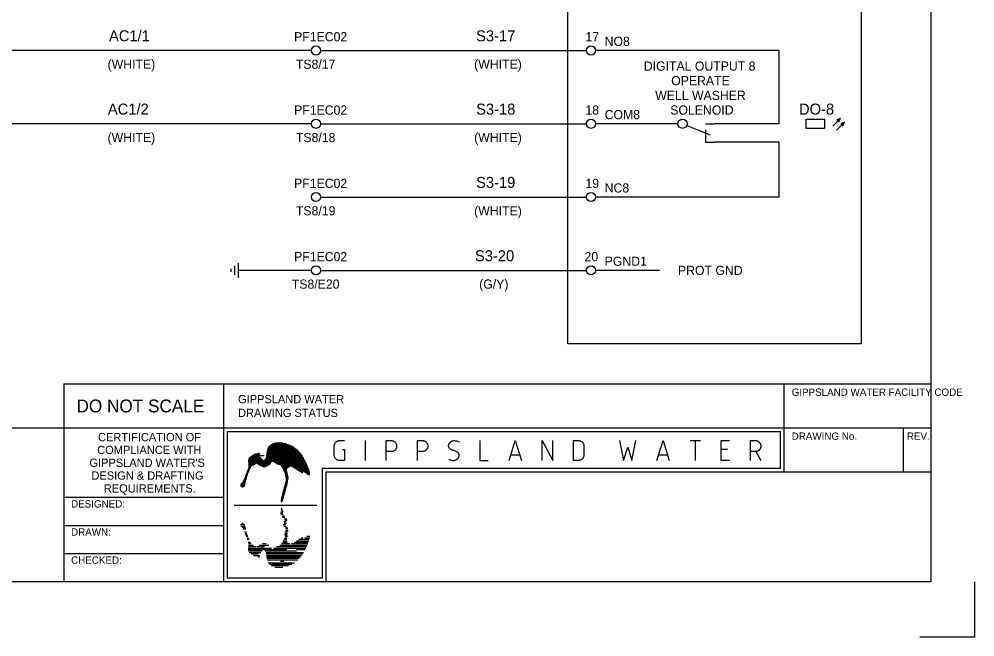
# Model space of a CAD drawing. Extents: x 0 to 841, y 0 to 594.
# Drawn here: x 580.3 to 841, y 0 to 168.6 of the extents above; entities that cross this region are included whole.
import ezdxf

# ---------------------------------------------------------------- set-up
doc = ezdxf.new("R2010")
doc.units = 0
for name, color, linetype in [('A1BORDER', 7, 'Continuous'), ('Level 1', 7, 'Continuous'), ('Level 10', 7, 'Continuous')]:
    doc.layers.add(name, color=color, linetype=linetype)

msp = doc.modelspace()

# ---------------------------------------------------------------- linework, layer by layer
at = {"layer": 'A1BORDER'}
for p, q in [((829, 581), (829, 15)), ((592.5, 69), (592.5, 15)), ((592.5, 69), (829, 69)), ((636, 69), (636, 15)), ((789, 45), (789, 69)), ((28, 57), (829, 57)), ((637, 56), (788, 56)), ((637, 56), (637, 16)), ((788, 46), (788, 56)), ((821.5, 45), (821.5, 57)), ((648.74, 52.32), (654.24, 52.32)), ((649.02, 52.52), (653.76, 52.52)), ((649.39, 52.72), (653.15, 52.72)), ((650.01, 52.92), (652.2, 52.92)), ((644.18, 49.72), (645.89, 49.72)), ((644.54, 49.92), (645.36, 49.92)), ((645.37, 50.12), (645.86, 50.12)), ((647.71, 49.72), (657.31, 49.72)), ((647.75, 49.92), (657.17, 49.92)), ((647.78, 50.12), (657.02, 50.12)), ((647.81, 50.32), (656.86, 50.32)), ((647.85, 50.52), (656.69, 50.52)), ((647.88, 50.72), (656.5, 50.72)), ((647.91, 50.92), (656.3, 50.92)), ((647.96, 51.12), (656.08, 51.12)), ((648.03, 51.32), (655.85, 51.32)), ((648.12, 51.52), (655.59, 51.52)), ((648.23, 51.72), (655.31, 51.72)), ((648.37, 51.92), (655, 51.92)), ((648.53, 52.12), (654.64, 52.12)), ((642.73, 48.12), (658.25, 48.12)), ((642.74, 47.92), (658.35, 47.92)), ((642.75, 48.32), (646.79, 48.32)), ((642.79, 47.72), (649.08, 47.72)), ((642.81, 48.52), (646.55, 48.52)), ((642.83, 47.52), (648.95, 47.52)), ((642.85, 47.31), (644.88, 47.31)), ((642.87, 47.12), (644.57, 47.12)), ((642.9, 48.72), (646.37, 48.72)), ((643.04, 48.92), (646.16, 48.92)), ((643.26, 49.12), (645.9, 49.12)), ((643.54, 49.32), (645.57, 49.32)), ((643.85, 49.52), (647.09, 49.52)), ((645.14, 47.31), (648.83, 47.31)), ((645.49, 47.12), (648.67, 47.12)), ((647.19, 48.32), (658.14, 48.32)), ((647.42, 48.52), (658.03, 48.52)), ((647.54, 48.72), (657.92, 48.72)), ((647.61, 48.92), (657.8, 48.92)), ((647.63, 49.12), (657.68, 49.12)), ((647.66, 49.32), (657.57, 49.32)), ((647.69, 49.52), (657.44, 49.52)), ((649.72, 47.72), (658.45, 47.72)), ((650.12, 47.52), (658.55, 47.52)), ((650.48, 47.31), (658.64, 47.31)), ((650.87, 47.12), (658.73, 47.12)), ((642.21, 44.52), (642.69, 44.52)), ((642.28, 44.72), (642.76, 44.72)), ((642.35, 44.92), (642.83, 44.92)), ((642.43, 45.12), (642.9, 45.12)), ((642.5, 45.32), (643, 45.32)), ((642.57, 45.52), (643.1, 45.52)), ((642.65, 45.72), (643.2, 45.72)), ((642.72, 45.92), (643.3, 45.92)), ((642.79, 46.12), (643.4, 46.12)), ((642.84, 46.32), (643.5, 46.32)), ((642.87, 46.52), (643.6, 46.52)), ((642.88, 46.92), (644.23, 46.92)), ((642.88, 46.72), (643.83, 46.72)), ((645.76, 46.92), (648.42, 46.92)), ((646.05, 46.72), (648.11, 46.72)), ((646.62, 46.52), (647.67, 46.52)), ((651.36, 46.92), (658.82, 46.92)), ((651.76, 46.72), (658.9, 46.72)), ((651.88, 46.52), (654.15, 46.52)), ((651.99, 46.32), (653.71, 46.32)), ((652.1, 46.12), (653.52, 46.12)), ((652.2, 45.92), (653.4, 45.92)), ((652.31, 45.72), (653.33, 45.72)), ((652.41, 45.52), (653.31, 45.52)), ((652.5, 45.32), (653.34, 45.32)), ((652.6, 45.12), (653.38, 45.12)), ((652.69, 44.92), (653.41, 44.92)), ((652.78, 44.72), (653.44, 44.72)), ((652.83, 44.52), (653.48, 44.52)), ((654.57, 46.52), (658.99, 46.52)), ((655, 46.32), (659.07, 46.32)), ((655.31, 46.12), (659.14, 46.12)), ((655.62, 45.92), (659.22, 45.92)), ((655.93, 45.72), (659.29, 45.72)), ((656.24, 45.52), (659.35, 45.52)), ((656.55, 45.32), (659.42, 45.32)), ((656.86, 45.12), (657.74, 45.12)), ((657.17, 44.92), (657.68, 44.92)), ((657.51, 44.72), (657.54, 44.72)), ((657.91, 45.12), (659.48, 45.12)), ((658.19, 44.92), (659.54, 44.92)), ((658.47, 44.72), (659.59, 44.72)), ((658.75, 44.52), (659.58, 44.52)), ((663, 46), (788, 46)), ((663, 16), (663, 46)), ((664, 45), (829, 45)), ((664, 15), (664, 45)), ((640.73, 41.72), (641.95, 41.72)), ((640.9, 41.92), (641.97, 41.92)), ((641.1, 42.12), (642, 42.12)), ((641.25, 42.31), (642.04, 42.31)), ((641.37, 42.52), (642.09, 42.52)), ((641.46, 42.72), (642.15, 42.72)), ((641.55, 42.92), (642.2, 42.92)), ((641.64, 43.12), (642.25, 43.12)), ((641.73, 43.32), (642.3, 43.32)), ((641.82, 43.51), (642.35, 43.51)), ((641.91, 43.72), (642.41, 43.72)), ((641.99, 43.92), (642.48, 43.92)), ((642.06, 44.12), (642.55, 44.12)), ((642.13, 44.32), (642.62, 44.32)), ((652.79, 41.72), (653.41, 41.72)), ((652.85, 41.92), (653.45, 41.92)), ((652.86, 44.32), (653.53, 44.32)), ((652.89, 44.12), (653.57, 44.12)), ((652.9, 42.12), (653.49, 42.12)), ((652.91, 43.92), (653.62, 43.92)), ((652.94, 43.72), (653.67, 43.72)), ((652.95, 42.31), (653.53, 42.31)), ((652.97, 43.51), (653.71, 43.51)), ((652.99, 42.52), (653.57, 42.52)), ((653, 43.32), (653.69, 43.32)), ((653.02, 43.12), (653.67, 43.12)), ((653.03, 42.72), (653.61, 42.72)), ((653.05, 42.92), (653.64, 42.92)), ((659.02, 44.32), (659.47, 44.32)), ((640.62, 41.32), (641.88, 41.32)), ((640.63, 41.52), (641.93, 41.52)), ((640.72, 41.12), (641.73, 41.12)), ((641.03, 40.92), (641.43, 40.92)), ((652.09, 39.12), (652.72, 39.12)), ((652.14, 39.32), (652.77, 39.32)), ((652.2, 39.52), (652.82, 39.52)), ((652.25, 39.72), (652.88, 39.72)), ((652.3, 39.92), (652.93, 39.92)), ((652.36, 40.12), (652.99, 40.12)), ((652.41, 40.32), (653.04, 40.32)), ((652.47, 40.52), (653.1, 40.52)), ((652.52, 40.72), (653.15, 40.72)), ((652.57, 40.92), (653.2, 40.92)), ((652.63, 41.12), (653.26, 41.12)), ((652.68, 41.32), (653.31, 41.32)), ((652.74, 41.52), (653.37, 41.52)), ((636, 38), (592.5, 38)), ((651.63, 37.32), (652.23, 37.32)), ((651.64, 37.12), (652.17, 37.12)), ((651.65, 37.52), (652.28, 37.52)), ((651.71, 37.72), (652.34, 37.72)), ((651.76, 37.92), (652.39, 37.92)), ((651.79, 36.92), (651.9, 36.92)), ((651.82, 38.12), (652.44, 38.12)), ((651.87, 38.32), (652.5, 38.32)), ((651.92, 38.52), (652.55, 38.52)), ((651.98, 38.72), (652.61, 38.72)), ((652.03, 38.92), (652.66, 38.92)), ((638.93, 35.98), (661.47, 35.98)), ((651.63, 34.64), (652.23, 34.64)), ((651.71, 34.24), (652.34, 34.24)), ((651.79, 35.04), (651.9, 35.04)), ((651.54, 33.84), (652.17, 33.84)), ((651.65, 33.44), (652.28, 33.44)), ((652.03, 33.04), (652.66, 33.04)), ((652.14, 32.64), (652.77, 32.64)), ((652.47, 31.44), (653.1, 31.44)), ((652.66, 32.24), (653.29, 32.24)), ((652.77, 31.84), (653.4, 31.84)), ((636, 30.34), (592.5, 30.34)), ((640.62, 30.64), (641.88, 30.64)), ((640.73, 30.24), (641.95, 30.24)), ((641.03, 31.04), (641.43, 31.04)), ((641.1, 29.84), (642, 29.84)), ((641.37, 29.44), (642.09, 29.44)), ((652.34, 30.64), (652.97, 30.64)), ((652.45, 30.24), (653.07, 30.24)), ((652.57, 31.04), (653.2, 31.04)), ((652.9, 29.84), (653.49, 29.84)), ((652.99, 29.44), (653.57, 29.44)), ((653.05, 29.04), (653.64, 29.04)), ((641.73, 28.64), (642.3, 28.64)), ((641.91, 28.24), (642.41, 28.24)), ((642.06, 27.84), (642.55, 27.84)), ((642.21, 27.44), (642.69, 27.44)), ((642.35, 27.04), (642.83, 27.04)), ((642.5, 26.64), (643, 26.64)), ((652.31, 26.24), (653.33, 26.24)), ((652.5, 26.64), (653.34, 26.64)), ((652.66, 27.84), (653.35, 27.84)), ((652.69, 27.04), (653.41, 27.04)), ((652.72, 28.24), (653.44, 28.24)), ((652.77, 28.64), (653.46, 28.64)), ((652.83, 27.44), (653.48, 27.44)), ((655.93, 26.24), (659.29, 26.24)), ((656.55, 26.64), (659.42, 26.64)), ((657.17, 27.04), (657.68, 27.04)), ((658.19, 27.04), (659.54, 27.04)), ((658.75, 27.44), (659.58, 27.44)), ((642.73, 23.84), (653.27, 23.84)), ((642.79, 25.84), (643.4, 25.84)), ((642.79, 24.24), (649.08, 24.24)), ((642.85, 24.65), (644.88, 24.65)), ((642.87, 25.44), (643.6, 25.44)), ((642.88, 25.04), (644.23, 25.04)), ((645.14, 24.65), (647.18, 24.65)), ((645.76, 25.04), (648.42, 25.04)), ((646.62, 25.44), (647.67, 25.44)), ((649.72, 24.24), (658.45, 24.24)), ((650.48, 24.65), (658.64, 24.65)), ((651.36, 25.04), (658.82, 25.04)), ((651.88, 25.44), (654.15, 25.44)), ((652.1, 25.84), (653.52, 25.84)), ((654.57, 25.44), (658.99, 25.44)), ((655.31, 25.84), (659.14, 25.84)), ((655.94, 23.84), (658.25, 23.84)), ((636, 22.67), (592.5, 22.67)), ((642.81, 23.44), (646.55, 23.44)), ((643.04, 23.04), (646.16, 23.04)), ((643.54, 22.64), (645.57, 22.64)), ((644.18, 22.24), (645.89, 22.24)), ((645.37, 21.84), (645.86, 21.84)), ((647.42, 23.44), (655.89, 23.44)), ((647.61, 23.04), (657.8, 23.04)), ((647.66, 22.64), (657.57, 22.64)), ((647.71, 22.24), (657.31, 22.24)), ((647.78, 21.84), (657.02, 21.84)), ((647.85, 21.44), (656.69, 21.44)), ((647.91, 21.04), (656.3, 21.04)), ((648.23, 20.24), (655.31, 20.24)), ((648.53, 19.84), (654.64, 19.84)), ((649.02, 19.44), (653.76, 19.44)), ((650.01, 19.04), (652.2, 19.04)), ((651.57, 20.64), (652.44, 20.64)), ((663, 16), (637, 16)), ((829, 15), (28, 15)), ((829, 15), (829, 15)), ((841, 0), (841, 15)), ((826, 0), (841, 0))]:
    msp.add_line(p, q, dxfattribs=at)
for points in [[(668.49, 51.15), (669.06, 51.15), (669.06, 48.16), (667.64, 48.16), (667.51, 48.16), (667.39, 48.18), (667.28, 48.21), (667.15, 48.25), (667.04, 48.3), (666.93, 48.36), (666.82, 48.43), (666.73, 48.51), (666.64, 48.6), (666.55, 48.7), (666.48, 48.8), (666.41, 48.91), (666.35, 49.02), (666.31, 49.14), (666.27, 49.27), (666.24, 49.39), (666.22, 49.52), (666.22, 49.66), (666.22, 52.05), (666.22, 52.18), (666.24, 52.31), (666.27, 52.43), (666.31, 52.56), (666.35, 52.67), (666.41, 52.79), (666.48, 52.9), (666.55, 53), (666.64, 53.1), (666.73, 53.19), (666.82, 53.27), (666.93, 53.34), (667.04, 53.4), (667.15, 53.45), (667.28, 53.49), (667.39, 53.52), (667.51, 53.54), (667.64, 53.54), (669.06, 53.54)], [(674.74, 48.16), (674.74, 53.54)], [(680.42, 48.16), (680.42, 53.54), (681.84, 53.54), (681.96, 53.54), (682.08, 53.52), (682.2, 53.49), (682.32, 53.45), (682.43, 53.4), (682.54, 53.34), (682.65, 53.27), (682.74, 53.19), (682.84, 53.1), (682.92, 53), (682.99, 52.9), (683.06, 52.79), (683.12, 52.67), (683.17, 52.56), (683.21, 52.43), (683.23, 52.31), (683.25, 52.18), (683.26, 52.05), (683.25, 51.91), (683.23, 51.78), (683.21, 51.66), (683.17, 51.53), (683.12, 51.42), (683.06, 51.3), (682.99, 51.19), (682.92, 51.09), (682.84, 50.99), (682.74, 50.9), (682.65, 50.82), (682.54, 50.75), (682.43, 50.69), (682.32, 50.64), (682.2, 50.6), (682.08, 50.57), (681.96, 50.55), (681.84, 50.55), (680.42, 50.55)], [(688.93, 48.16), (688.93, 53.54), (690.35, 53.54), (690.47, 53.54), (690.59, 53.52), (690.71, 53.49), (690.83, 53.45), (690.94, 53.4), (691.05, 53.34), (691.16, 53.27), (691.26, 53.19), (691.35, 53.1), (691.43, 53), (691.51, 52.9), (691.57, 52.79), (691.63, 52.67), (691.68, 52.56), (691.72, 52.43), (691.75, 52.31), (691.76, 52.18), (691.77, 52.05), (691.76, 51.91), (691.75, 51.78), (691.72, 51.66), (691.68, 51.53), (691.63, 51.42), (691.57, 51.3), (691.51, 51.19), (691.43, 51.09), (691.35, 50.99), (691.26, 50.9), (691.16, 50.82), (691.05, 50.75), (690.94, 50.69), (690.83, 50.64), (690.71, 50.6), (690.59, 50.57), (690.47, 50.55), (690.35, 50.55), (688.93, 50.55)], [(697.45, 48.46), (697.67, 48.36), (697.9, 48.27), (698.12, 48.21), (698.36, 48.17), (698.6, 48.16), (698.84, 48.16), (698.87, 48.16), (699.03, 48.18), (699.18, 48.21), (699.33, 48.26), (699.48, 48.32), (699.62, 48.4), (699.72, 48.46), (699.81, 48.53), (699.9, 48.61), (699.98, 48.69), (700.05, 48.78), (700.11, 48.88), (700.17, 48.99), (700.22, 49.09), (700.25, 49.21), (700.28, 49.32), (700.29, 49.36), (700.3, 49.44), (700.3, 49.52), (700.3, 49.61), (700.29, 49.69), (700.27, 49.77), (700.25, 49.86), (700.22, 49.93), (700.18, 50.01), (700.14, 50.09), (700.09, 50.15), (700.04, 50.21), (700.01, 50.25), (699.85, 50.39), (699.69, 50.51), (699.52, 50.61), (699.34, 50.7), (699.15, 50.78), (698.95, 50.83), (698.87, 50.85), (698.68, 50.9), (698.49, 50.96), (698.3, 51.04), (698.12, 51.14), (697.96, 51.26), (697.8, 51.39), (697.73, 51.45), (697.67, 51.51), (697.62, 51.57), (697.58, 51.64), (697.53, 51.71), (697.5, 51.79), (697.47, 51.87), (697.46, 51.95), (697.44, 52.04), (697.43, 52.12), (697.43, 52.21), (697.44, 52.29), (697.45, 52.35), (697.47, 52.46), (697.51, 52.58), (697.55, 52.69), (697.61, 52.79), (697.67, 52.89), (697.74, 52.99), (697.82, 53.07), (697.9, 53.15), (697.99, 53.23), (698.02, 53.24), (698.15, 53.33), (698.3, 53.4), (698.44, 53.45), (698.6, 53.5), (698.75, 53.52), (698.87, 53.54), (699.11, 53.55), (699.35, 53.53), (699.58, 53.49), (699.82, 53.43), (700.04, 53.35), (700.27, 53.25)], [(705.96, 53.54), (705.96, 48.16), (708.23, 48.16)], [(713.91, 48.16), (715.61, 53.54), (717.32, 48.16)], [(722.99, 48.16), (722.99, 53.54), (725.83, 48.16), (725.83, 53.54)], [(731.52, 48.16), (731.52, 53.54), (732.94, 53.54), (733.06, 53.54), (733.18, 53.52), (733.3, 53.49), (733.42, 53.45), (733.53, 53.4), (733.64, 53.34), (733.75, 53.27), (733.84, 53.19), (733.94, 53.1), (734.02, 53), (734.09, 52.9), (734.16, 52.79), (734.22, 52.67), (734.27, 52.56), (734.31, 52.43), (734.33, 52.31), (734.35, 52.18), (734.36, 52.05), (734.36, 49.66), (734.35, 49.52), (734.33, 49.39), (734.31, 49.27), (734.27, 49.14), (734.22, 49.02), (734.16, 48.91), (734.09, 48.8), (734.02, 48.7), (733.94, 48.6), (733.84, 48.51), (733.75, 48.43), (733.64, 48.36), (733.53, 48.3), (733.42, 48.25), (733.3, 48.21), (733.18, 48.18), (733.06, 48.16), (732.94, 48.16), (731.52, 48.16)], [(744.01, 53.54), (745.14, 48.16), (746.28, 51.75), (747.41, 48.16), (748.55, 53.54)], [(754.22, 48.16), (755.92, 53.54), (757.63, 48.16)], [(763.31, 53.54), (766.15, 53.54)], [(764.73, 53.54), (764.73, 48.16)], [(774.09, 48.16), (771.82, 48.16), (771.82, 53.54), (774.09, 53.54)], [(779.78, 48.16), (779.78, 53.54), (781.2, 53.54), (781.32, 53.54), (781.44, 53.52), (781.56, 53.49), (781.68, 53.45), (781.79, 53.4), (781.9, 53.34), (782.01, 53.27), (782.1, 53.19), (782.2, 53.1), (782.28, 53), (782.35, 52.9), (782.42, 52.79), (782.48, 52.67), (782.53, 52.56), (782.56, 52.43), (782.59, 52.31), (782.61, 52.18), (782.61, 52.05), (782.61, 51.91), (782.59, 51.78), (782.56, 51.66), (782.53, 51.53), (782.48, 51.42), (782.42, 51.3), (782.35, 51.19), (782.28, 51.09), (782.2, 50.99), (782.1, 50.9), (782.01, 50.82), (781.9, 50.75), (781.79, 50.69), (781.68, 50.64), (781.56, 50.6), (781.44, 50.57), (781.32, 50.55), (781.2, 50.55), (779.78, 50.55)], [(714.48, 49.66), (716.75, 49.66)], [(754.79, 49.66), (757.06, 49.66)], [(773.53, 51.15), (771.82, 51.15)], [(781.2, 50.55), (782.61, 48.16)]]:
    msp.add_lwpolyline(points, dxfattribs=at)
at = {"layer": 'Level 1'}
for p, q in [((660, 160), (360, 160)), ((662.5, 160), (735, 160)), ((787.5, 160), (737.5, 160)), ((787.5, 160), (787.5, 140)), ((660, 140), (360, 140)), ((662.5, 140), (735, 140)), ((760, 140), (737.5, 140)), ((787.5, 140), (770, 140)), ((787.5, 135), (770, 135)), ((787.5, 135), (787.5, 120)), ((662.5, 120), (735, 120)), ((787.5, 120), (737.5, 120)), ((660, 100), (640, 100)), ((662.5, 100), (735, 100)), ((755, 100), (737.5, 100))]:
    msp.add_line(p, q, dxfattribs=at)
for points in [[(730, 540), (810, 540), (810, 80), (730, 80)], [(795, 141.25), (800, 141.25), (800, 138.75), (795, 138.75)]]:
    msp.add_lwpolyline(points, close=True, dxfattribs=at)
for centre in [(661.25, 160), (736.25, 160), (661.25, 140), (736.25, 140), (661.25, 120), (736.25, 120), (661.25, 100), (736.25, 100)]:
    msp.add_circle(centre, 1.25, dxfattribs=at)
at = {"layer": 'Level 10'}
for p, q in [((802.23, 139.35), (804.36, 141.48)), ((803.46, 141.08), (804.17, 141.08)), ((803.5, 140.93), (804.11, 140.93)), ((803.79, 141.22), (804.24, 141.22)), ((804.12, 141.38), (804.31, 141.38)), ((762.41, 139.54), (768.75, 137)), ((767.5, 140), (770, 140)), ((767.5, 138.37), (767.5, 135)), ((803.29, 138.3), (805.41, 140.42)), ((803.64, 140.78), (804.03, 140.78)), ((803.8, 140.62), (803.97, 140.62)), ((804.52, 140.02), (805.23, 140.02)), ((804.56, 139.87), (805.16, 139.87)), ((804.71, 139.72), (805.1, 139.72)), ((804.85, 140.16), (805.3, 140.16)), ((804.86, 139.56), (805.03, 139.56)), ((805.18, 140.31), (805.37, 140.31)), ((767.5, 135), (770, 135)), ((640, 102), (640, 98)), ((638, 100.4), (638, 99.6)), ((639, 101.2), (639, 98.8))]:
    msp.add_line(p, q, dxfattribs=at)
for points in [[(804.36, 141.48), (803.38, 141.04), (803.91, 140.5)], [(805.41, 140.42), (804.44, 139.98), (804.98, 139.44)]]:
    msp.add_lwpolyline(points, close=True, dxfattribs=at)
msp.add_circle((761.25, 140), 1.25, dxfattribs=at)

# ---------------------------------------------------------------- texts
at = {"layer": 'A1BORDER'}
for s, height, p in [('GIPPSLAND WATER FACILITY CODE', 2, (791.03, 65.77)), ('GIPPSLAND WATER', 2.25, (640, 63.75)), ('DO NOT SCALE', 3.5, (595.92, 61.25)), ('DRAWING STATUS', 2.25, (640, 60)), ('CERTIFICATION OF', 2.25, (601.79, 53.39)), ('DRAWING No.', 2, (791.03, 53.77)), ('REV.', 2, (822.43, 53.77)), ('COMPLIANCE WITH', 2.25, (601.57, 49.89)), ("GIPPSLAND WATER'S", 2.25, (599.45, 46.39)), ('DESIGN & DRAFTING', 2.25, (600, 42.89)), ('REQUIREMENTS.', 2.25, (603.37, 39.39)), ('DESIGNED:', 2, (594.44, 35.29)), ('DRAWN:', 2, (594.44, 27.62)), ('CHECKED:', 2, (594.44, 19.95))]:
    msp.add_text(s, height=height, dxfattribs=at).set_placement(p)
at = {"layer": 'Level 1'}
for s, height, p in [('AC1/1', 3, (604.78, 162.5)), ('PF1EC02', 2.5, (655.28, 162.5)), ('S3-17', 3, (704.93, 162.5)), ('17', 2.5, (734.75, 162.5)), ('NO8', 2.5, (740, 161.25)), ('(WHITE)', 2.5, (604.4, 155)), ('TS8/17', 2.5, (655.77, 155)), ('(WHITE)', 2.5, (704.4, 155)), ('DIGITAL OUTPUT 8', 2.5, (750.68, 154.5)), ('OPERATE', 2.5, (758.15, 150.5)), ('WELL WASHER', 2.5, (753.79, 146.5)), ('AC1/2', 3, (604.48, 142.5)), ('PF1EC02', 2.5, (655.28, 142.5)), ('S3-18', 3, (704.93, 142.5)), ('18', 2.5, (734.75, 142.5)), ('COM8', 2.5, (740, 141.25)), ('SOLENOID', 2.5, (757.9, 142.5)), ('DO-8', 3, (793.02, 142.5)), ('(WHITE)', 2.5, (604.39, 135)), ('TS8/18', 2.5, (655.77, 135)), ('(WHITE)', 2.5, (704.4, 135)), ('S3-19', 3, (704.93, 122.5)), ('PF1EC02', 2.5, (655.28, 122.5)), ('19', 2.5, (734.75, 122.5)), ('NC8', 2.5, (740, 121.25)), ('TS8/19', 2.5, (655.77, 115)), ('(WHITE)', 2.5, (704.4, 115)), ('PF1EC02', 2.5, (655.28, 102.5)), ('S3-20', 3, (704.62, 102.5)), ('20', 2.5, (734.51, 102.5)), ('PGND1', 2.5, (740, 101.25)), ('PROT GND', 2.5, (760, 98.75)), ('TS8/E20', 2.5, (654.65, 95)), ('(G/Y)', 2.5, (705.77, 95))]:
    msp.add_text(s, height=height, dxfattribs=at).set_placement(p)

doc.saveas('drawing.dxf')
